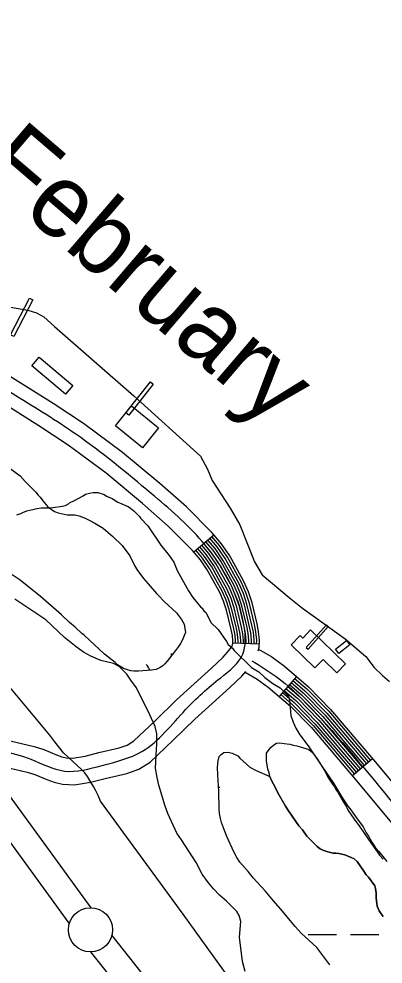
# Model space of a CAD drawing. Extents: x 3161564 to 3199464, y 849354 to 874788.
# Drawn here: x 3177223 to 3177635, y 855355 to 856425 of the extents above; entities that cross this region are included whole.
import ezdxf

# ---------------------------------------------------------------- set-up
doc = ezdxf.new("R2010")
doc.units = 0
for name, color, linetype in [('V-BLDG-OTLN', 7, 'Continuous'), ('V-CHAN-DOCK', 7, 'Continuous'), ('V-LEVE-TOET', 7, 'Continuous'), ('V-RIVR-IDEN', 7, 'Continuous'), ('V-ROAD-CNTR', 7, 'Continuous'), ('V-SITE-VEGE', 7, 'Continuous'), ('V-SURV-LINE', 7, 'Continuous'), ('V-TOPO-SHOR', 7, 'Continuous'), ('V-WETL-SWMP', 7, 'Continuous')]:
    doc.layers.add(name, color=color, linetype=linetype)

msp = doc.modelspace()

# ---------------------------------------------------------------- linework, layer by layer
at = {"layer": 'V-BLDG-OTLN'}
for points in [[(3177276.2, 856000.2), (3177238, 856032.1), (3177246.3, 856042), (3177284.5, 856010.1)], [(3177363.2, 855939.5), (3177332.5, 855964.4), (3177350.6, 855986.8), (3177381.3, 855961.9)], [(3177593, 855694.7), (3177583.2, 855684.6), (3177567.5, 855699.8), (3177558.2, 855690.3), (3177531.3, 855716.4), (3177541.6, 855727), (3177544.6, 855724.1), (3177553.5, 855733.2)]]:
    msp.add_lwpolyline(points, close=True, dxfattribs=at)
at = {"layer": 'V-CHAN-DOCK'}
for points in [[(3177213.9, 856067.4), (3177235.5, 856108.9), (3177239.1, 856107.1), (3177217.6, 856065.5), (3177213.9, 856067.4)], [(3177344.3, 855978.9), (3177372.1, 856014), (3177375.4, 856011.3), (3177347.7, 855976.3), (3177344.3, 855978.9)], [(3177550.8, 855711.3), (3177573.5, 855737.3), (3177571.4, 855739.2), (3177548.6, 855713.2), (3177550.8, 855711.3)], [(3177581.7, 855711.4), (3177594, 855721.1), (3177597.7, 855716.4), (3177585.4, 855706.7), (3177581.7, 855711.4)]]:
    msp.add_lwpolyline(points, dxfattribs=at)
at = {"layer": 'V-LEVE-TOET'}
for points in [[(3177304.8, 855560.8), (3177300.9, 855567.2), (3177297.9, 855571.3), (3177294.1, 855575.4), (3177273.7, 855594.2), (3177264, 855606.4), (3177258.3, 855614.1), (3177215, 855666.3), (3177175.3, 855706.7), (3177129.5, 855747.9), (3177034.4, 855820.9), (3176906.9, 855909.7), (3176744.5, 856013), (3176646.2, 856081), (3176636.6, 856089.2), (3176622.9, 856101.9), (3176611.6, 856113.2), (3176549.5, 856179.9), (3176488.5, 856246.6)], [(3177895, 854786.5), (3177827, 854872.8), (3177751.9, 854967.9), (3177672.1, 855062.6), (3177580.1, 855181.8), (3177482, 855310.4), (3177409.2, 855411.4), (3177315.8, 855539.5), (3177313.2, 855545.8), (3177310, 855552), (3177307.8, 855555.9), (3177304.8, 855560.8)]]:
    msp.add_lwpolyline(points, dxfattribs=at)
at = {"layer": 'V-ROAD-CNTR'}
for p, q in [((3177421.2, 855821.5), (3177444.1, 855840.8)), ((3177465.4, 855718.7), (3177495.4, 855717.4)), ((3177537.3, 855680.7), (3177517.7, 855657.9)), ((3177623.6, 855587.3), (3177600.7, 855567.9))]:
    msp.add_line(p, q, dxfattribs=at)
for points in [[(3177494.1, 855709.5), (3177495.2, 855713.8), (3177495.6, 855721.7), (3177494.6, 855731.4), (3177492.9, 855740.1), (3177487.2, 855764), (3177483, 855776.5), (3177477.6, 855788.9), (3177462, 855817.2), (3177452.5, 855830.8), (3177441.8, 855843.5), (3177412.9, 855872.5), (3177382.8, 855899.2), (3177340.5, 855934.2), (3177296.4, 855967.1), (3177262.1, 855989.6), (3177227.7, 856011.2), (3177194.2, 856031.7)], [(3177207, 855609.1), (3177240.7, 855601.4), (3177251.6, 855597.9), (3177266, 855591.8), (3177272, 855589.6), (3177276.9, 855588.4), (3177284.4, 855588.1), (3177298.3, 855590.3), (3177313.9, 855594.3), (3177336.9, 855599.7), (3177345.9, 855602.9), (3177353.4, 855607.6), (3177377.3, 855630.1), (3177401.6, 855654), (3177421.8, 855672.3), (3177441.6, 855690.2), (3177454.2, 855702.1), (3177459.4, 855707.9), (3177464, 855713.9), (3177464.5, 855714.9), (3177465.4, 855718.3), (3177465.5, 855720.8), (3177464.9, 855727.1), (3177463.6, 855733.8), (3177458.3, 855755.7), (3177455, 855765.8), (3177450.7, 855775.6), (3177436.5, 855801.3), (3177428.7, 855812.6), (3177419.7, 855823.2), (3177392.4, 855850.6), (3177363.2, 855876.4), (3177322, 855910.7), (3177279.2, 855942.5), (3177245.9, 855964.3), (3177211.9, 855985.7)], [(3177477.4, 855718.2), (3177477.5, 855721.2), (3177476.8, 855728.8), (3177475.3, 855736.3), (3177469.9, 855759), (3177466.2, 855770.1), (3177461.5, 855780.9), (3177446.7, 855807.7), (3177438.2, 855819.9), (3177430.3, 855829.2)], [(3177480.4, 855718.1), (3177480.6, 855721.3), (3177479.7, 855729.3), (3177478.3, 855737), (3177472.8, 855759.9), (3177469, 855771.2), (3177464.2, 855782.3), (3177449.2, 855809.3), (3177440.6, 855821.7), (3177432.6, 855831.2)], [(3177483.4, 855717.9), (3177483.6, 855721.4), (3177482.7, 855729.7), (3177481.2, 855737.6), (3177475.7, 855760.7), (3177471.8, 855772.2), (3177466.9, 855783.6), (3177451.8, 855810.9), (3177443, 855823.5), (3177434.9, 855833.1)], [(3177486.4, 855717.8), (3177486.6, 855721.5), (3177485.7, 855730.1), (3177484.1, 855738.2), (3177478.6, 855761.5), (3177474.6, 855773.3), (3177469.6, 855784.9), (3177454.3, 855812.4), (3177445.4, 855825.4), (3177437.2, 855835)], [(3177489.4, 855717.7), (3177489.6, 855721.6), (3177488.7, 855730.6), (3177487.1, 855738.8), (3177481.4, 855762.3), (3177477.4, 855774.4), (3177472.3, 855786.3), (3177456.9, 855814), (3177447.8, 855827.2), (3177439.5, 855837)], [(3177492.4, 855717.6), (3177492.6, 855721.6), (3177491.6, 855731), (3177490, 855739.5), (3177484.3, 855763.2), (3177480.2, 855775.5), (3177474.9, 855787.6), (3177459.4, 855815.6), (3177450.2, 855829), (3177441.8, 855838.9)], [(3177468.4, 855718.6), (3177468.5, 855720.9), (3177467.9, 855727.5), (3177466.5, 855734.4), (3177461.2, 855756.5), (3177457.8, 855766.9), (3177453.4, 855777), (3177439, 855802.9), (3177431.1, 855814.4), (3177423.5, 855823.4)], [(3177471.4, 855718.5), (3177471.5, 855721), (3177470.8, 855728), (3177469.5, 855735.1), (3177464.1, 855757.4), (3177460.6, 855767.9), (3177456.1, 855778.3), (3177441.6, 855804.5), (3177433.5, 855816.2), (3177425.8, 855825.4)], [(3177474.4, 855718.3), (3177474.5, 855721.1), (3177473.8, 855728.4), (3177472.4, 855735.7), (3177467, 855758.2), (3177463.4, 855769), (3177458.8, 855779.6), (3177444.1, 855806.1), (3177435.8, 855818.1), (3177428.1, 855827.3)], [(3177494.6, 855711.3), (3177509.5, 855702.6), (3177523.9, 855692.2), (3177551.2, 855668.7), (3177576.1, 855643.2), (3177624.6, 855586.1), (3177672.3, 855529.2), (3177736.6, 855452.1), (3177800.7, 855374.8)], [(3177188.7, 855582.4), (3177200.4, 855579.8), (3177232.8, 855572.4), (3177241.2, 855569.7), (3177255, 855563.9), (3177263.2, 855560.9), (3177272.7, 855558.6), (3177286.2, 855558), (3177304.5, 855560.9), (3177321, 855565.2), (3177345.4, 855570.9), (3177359, 855575.8), (3177371.8, 855583.7), (3177398.1, 855608.4), (3177422.3, 855632.2), (3177441.9, 855650), (3177461.9, 855668.2), (3177475.6, 855681), (3177480.1, 855686.1)], [(3177479.4, 855685.4), (3177493.1, 855677.4), (3177505.3, 855668.6), (3177530.7, 855646.8), (3177553.9, 855623), (3177601.6, 855566.8), (3177649.3, 855510), (3177713.5, 855432.9), (3177777.6, 855355.6)], [(3177527.5, 855669.3), (3177540.9, 855657.7), (3177565, 855633.1), (3177612.2, 855577.6)], [(3177529.5, 855671.6), (3177543, 855659.9), (3177567.3, 855635.1), (3177614.4, 855579.5)], [(3177531.4, 855673.8), (3177545.1, 855662.1), (3177569.5, 855637.1), (3177616.7, 855581.5)], [(3177533.4, 855676.1), (3177547.1, 855664.3), (3177571.7, 855639.1), (3177619, 855583.4)], [(3177535.3, 855678.4), (3177549.2, 855666.5), (3177573.9, 855641.2), (3177621.3, 855585.4)], [(3177519.7, 855660.2), (3177532.7, 855649), (3177556.2, 855625), (3177603, 855569.8)], [(3177521.6, 855662.5), (3177534.8, 855651.2), (3177558.4, 855627), (3177605.3, 855571.8)], [(3177523.6, 855664.7), (3177536.8, 855653.4), (3177560.6, 855629), (3177607.6, 855573.7)], [(3177525.6, 855667), (3177538.9, 855655.5), (3177562.8, 855631.1), (3177609.9, 855575.6)]]:
    msp.add_lwpolyline(points, dxfattribs=at)
for points in [[(3176879.1, 855651.9), (3176902.3, 855659.1), (3176934.1, 855667), (3176983.4, 855657.7), (3177040.7, 855639.1), (3177110.5, 855613.6), (3177170.6, 855601.8), (3177236.8, 855586.9), (3177274.8, 855573.5), (3177317.4, 855579.8), (3177362.6, 855595.7), (3177412, 855643.1), (3177451.7, 855679.2), (3177476.7, 855705.8), (3177478.3, 855737), (3177464.2, 855782.3), (3177430.8, 855833.4), (3177373, 855887.8), (3177287.8, 855954.8), (3177219.8, 855998.4), (3177153, 856039.4), (3177089.3, 856079.2), (3177023.4, 856134.3), (3176966.6, 856207.9), (3176895.2, 856290.1), (3176782.2, 856425.1), (3176693.2, 856545.3), (3176615.2, 856622.6), (3176543.9, 856726.5), (3176474.4, 856784.2), (3176414.4, 856823.6), (3176395.9, 856828), (3176350.8, 856806.2), (3176279.1, 856754.7), (3176211.6, 856707.4), (3176172.3, 856696.1), (3176141.1, 856702), (3176111.7, 856719.6), (3176032.6, 856777.4), (3175933.6, 856857.4), (3175839, 856930.3), (3175807.1, 856951.5), (3175770.1, 856958.7), (3175787.1, 856991.4), (3175795.1, 857040.7), (3175799.5, 857113.7), (3175810.8, 857206.9), (3175813.7, 857287.4), (3175807.8, 857386.8), (3175805.7, 857497.9), (3175801.9, 857543.6), (3175783.5, 857620.5), (3175760.2, 857716.1), (3175755.3, 857765.5), (3175754.5, 857815.6), (3175751.7, 857884.3), (3175756.3, 858015.5), (3175754.9, 858158.6), (3175753.1, 858270.8), (3175748.6, 858321.7), (3175736.5, 858372), (3175677.2, 858555.5), (3175602.2, 858747.1), (3175558.2, 858866.9), (3175502.5, 858986.2), (3175436.3, 859092.6), (3175371.2, 859185.1), (3175300.7, 859261.6), (3175219.1, 859367.2), (3175166.2, 859443.7), (3175175.3, 859507.1), (3175222, 859537.9), (3175285.3, 859568.3), (3175321.2, 859607.5), (3175310.3, 859667.2), (3175262.4, 859798.6), (3175224.6, 859877.9), (3175174.7, 859982), (3175144.8, 860115.4), (3175122.6, 860284.8), (3175088.4, 860568.6), (3175086.3, 860704.5), (3175072.2, 860854.5), (3175052.5, 860999.9), (3175047.5, 861166.8), (3175053.2, 861343.7), (3175066.7, 861550.4), (3175065.5, 861662.5), (3175040.2, 861767.8), (3175017.8, 861884.2), (3175008.4, 862033.9), (3174979.6, 862160.3), (3174952.1, 862274.6), (3174921.6, 862422.8), (3174897, 862525.5), (3174861.7, 862663.2), (3174841.1, 862738)], [(3177487, 855698.4), (3177514.6, 855680.4), (3177565, 855633.1), (3177660.8, 855519.6), (3177789.2, 855365.2)]]:
    msp.add_spline(points, degree=3, dxfattribs=at)
at = {"layer": 'V-SITE-VEGE'}
for p, q in [((3177286.2, 855879.9), (3177296.2, 855885)), ((3177296.2, 855885), (3177298.7, 855886.9)), ((3177298.7, 855886.9), (3177303.1, 855888.2)), ((3177303.1, 855888.2), (3177307.5, 855888.8)), ((3177307.5, 855888.8), (3177312.5, 855888.9)), ((3177312.5, 855888.9), (3177320, 855886.4)), ((3177320, 855886.4), (3177322.6, 855884.6)), ((3177322.6, 855884.6), (3177328.9, 855882.1)), ((3177258.7, 855871.5), (3177269.9, 855872.8)), ((3177269.9, 855872.8), (3177276.2, 855874.1)), ((3177276.2, 855874.1), (3177279.3, 855876)), ((3177279.3, 855876), (3177280.6, 855877.3)), ((3177280.6, 855877.3), (3177286.2, 855879.9)), ((3177328.9, 855882.1), (3177335.2, 855877.8)), ((3177335.2, 855877.8), (3177338.9, 855876.5)), ((3177338.9, 855876.5), (3177344, 855874.1)), ((3177344, 855874.1), (3177347.1, 855872.8)), ((3177347.1, 855872.8), (3177349.7, 855871)), ((3177221.1, 855863.6), (3177225.4, 855864.9)), ((3177225.4, 855864.9), (3177227.9, 855866.2)), ((3177227.9, 855866.2), (3177232.3, 855868.1)), ((3177232.3, 855868.1), (3177239.2, 855869.4)), ((3177239.2, 855869.4), (3177243.6, 855870.7)), ((3177243.6, 855870.7), (3177248.6, 855871.4)), ((3177248.6, 855871.4), (3177258.7, 855871.5)), ((3177349.7, 855871), (3177353.5, 855867.9)), ((3177353.5, 855867.9), (3177359.8, 855861.6)), ((3177359.8, 855861.6), (3177361, 855859.8)), ((3177361, 855859.8), (3177369.3, 855851)), ((3177369.3, 855851), (3177383.9, 855829.2)), ((3177383.9, 855829.2), (3177393.4, 855817.4)), ((3177393.4, 855817.4), (3177398.5, 855809.9)), ((3177398.5, 855809.9), (3177402.3, 855800.5)), ((3177402.3, 855800.5), (3177415.1, 855777.4)), ((3177415.1, 855777.4), (3177420.1, 855769.9)), ((3177254, 855744.7), (3177218.7, 855768.2)), ((3177420.1, 855769.9), (3177429, 855759.3)), ((3177429, 855759.3), (3177430.9, 855758)), ((3177430.9, 855758), (3177432.8, 855754.9)), ((3177432.8, 855754.9), (3177434.7, 855753)), ((3177274.9, 855724.8), (3177254, 855744.7)), ((3177434.7, 855753), (3177439.2, 855744.9)), ((3177439.2, 855744.9), (3177440.5, 855741.8)), ((3177440.5, 855741.8), (3177448.7, 855733.7)), ((3177448.7, 855733.7), (3177458.2, 855720)), ((3177288.2, 855714.2), (3177274.9, 855724.8)), ((3177296.4, 855708), (3177288.2, 855714.2)), ((3177458.2, 855720), (3177460.1, 855716.9)), ((3177460.1, 855716.9), (3177465.2, 855712.5)), ((3177465.2, 855712.5), (3177467.1, 855710)), ((3177304.6, 855703.7), (3177296.4, 855708)), ((3177315.9, 855698.7), (3177304.6, 855703.7)), ((3177467.1, 855710), (3177486.7, 855690.7)), ((3177330.4, 855695.1), (3177315.9, 855698.7)), ((3177336.7, 855692), (3177330.4, 855695.1)), ((3177345.5, 855683.3), (3177336.7, 855692)), ((3177486.7, 855690.7), (3177494.9, 855685.8)), ((3177350, 855676.4), (3177345.5, 855683.3)), ((3177494.9, 855685.8), (3177501.8, 855679.5)), ((3177501.8, 855679.5), (3177510.7, 855672.7)), ((3177356.3, 855667.7), (3177350, 855676.4)), ((3177510.7, 855672.7), (3177518.9, 855667.7)), ((3177371.6, 855637.1), (3177356.3, 855667.7)), ((3177518.9, 855667.7), (3177522, 855664.6)), ((3177522, 855664.6), (3177528.4, 855658.4)), ((3177528.4, 855658.4), (3177529.7, 855654)), ((3177529.7, 855654), (3177531.1, 855636.5)), ((3177377.4, 855623.9), (3177371.6, 855637.1)), ((3177531.1, 855636.5), (3177533.6, 855629)), ((3177533.6, 855629), (3177536.8, 855622.1)), ((3177379.3, 855615.8), (3177377.4, 855623.9)), ((3177379.4, 855603.9), (3177379.3, 855615.8)), ((3177536.8, 855622.1), (3177541.3, 855614.6)), ((3177541.3, 855614.6), (3177550.8, 855602.1)), ((3177377.8, 855576.9), (3177378.9, 855598.2)), ((3177378.9, 855598.2), (3177379.4, 855603.9)), ((3177550.8, 855602.1), (3177566, 855579)), ((3177379.7, 855566.2), (3177377.8, 855576.9)), ((3177566, 855579), (3177579.4, 855559.7)), ((3177381.7, 855557.4), (3177379.7, 855566.2)), ((3177388.8, 855533.6), (3177381.7, 855557.4)), ((3177579.4, 855559.7), (3177588.3, 855544.7)), ((3177588.3, 855544.7), (3177594.6, 855535.3)), ((3177392, 855525.5), (3177388.8, 855533.6)), ((3177594.6, 855535.3), (3177599.1, 855529.7)), ((3177599.1, 855529.7), (3177604.1, 855522.2)), ((3177402.2, 855503), (3177392, 855525.5)), ((3177604.1, 855522.2), (3177613, 855510.4)), ((3177613, 855510.4), (3177616.2, 855503.5)), ((3177407.3, 855495.5), (3177402.2, 855503)), ((3177616.2, 855503.5), (3177618.8, 855499.7)), ((3177618.8, 855499.7), (3177622.6, 855492.9)), ((3177423.8, 855469.9), (3177407.3, 855495.5)), ((3177622.6, 855492.9), (3177627, 855486.6)), ((3177627, 855486.6), (3177630.8, 855482.3)), ((3177630.8, 855482.3), (3177639.7, 855471)), ((3177430.8, 855456.8), (3177423.8, 855469.9)), ((3177437.8, 855446.8), (3177430.8, 855456.8)), ((3177443.5, 855440), (3177437.8, 855446.8)), ((3177450.5, 855433.1), (3177443.5, 855440)), ((3177458.1, 855426.3), (3177450.5, 855433.1)), ((3177470.1, 855414.4), (3177458.1, 855426.3)), ((3177472.6, 855410.1), (3177470.1, 855414.4)), ((3177474.6, 855403.2), (3177472.6, 855410.1)), ((3177472.8, 855385.6), (3177474.6, 855403.2)), ((3177476.2, 855358), (3177472.8, 855385.6)), ((3177479.4, 855346.7), (3177476.2, 855358))]:
    msp.add_line(p, q, dxfattribs=at)
at = {"layer": 'V-SURV-LINE'}
for points in [[(3177177, 855594.1), (3177304.6, 855418.8)], [(3177280.4, 855401.1), (3177152.7, 855576.4)], [(3177328.5, 855387.4), (3177753.7, 854849.5)], [(3177730.1, 854830.9), (3177304.9, 855368.8)]]:
    msp.add_lwpolyline(points, dxfattribs=at)
msp.add_circle((3177304.3, 855393.8), 25, dxfattribs=at)
at = {"layer": 'V-TOPO-SHOR'}
for points in [[(3176820, 856432.1), (3176835.5, 856422.6), (3176927.1, 856314), (3176937.7, 856303.1), (3176955.6, 856286.8), (3176967, 856280.5), (3176975.6, 856277), (3176991.9, 856271.4), (3177012.5, 856263.5), (3177022.6, 856258.7), (3177030.5, 856252.6), (3177038.5, 856244.6), (3177069.6, 856216), (3177111.9, 856189.1), (3177171, 856131.9), (3177206.5, 856101), (3177213.8, 856098.6), (3177233.3, 856095.3), (3177243.2, 856092.3), (3177251.7, 856087.6), (3177263.6, 856076.8), (3177353.4, 855998.1), (3177429, 855930.1), (3177436.7, 855915.1)], [(3177436.7, 855915.1), (3177441.9, 855902.3), (3177462.3, 855871.2), (3177473.3, 855852.2), (3177489.9, 855810.2), (3177498.5, 855795.7), (3177529.2, 855770), (3177544.1, 855757.8), (3177592.5, 855723.3), (3177615.8, 855703.1), (3177625.3, 855690.9), (3177634.9, 855681.5), (3177642.6, 855675)], [(3177507.3, 855567.5), (3177506.4, 855571.4), (3177504.9, 855575.6), (3177503.7, 855585.2), (3177503.7, 855593.7), (3177506.5, 855597.9), (3177508.7, 855600.5), (3177511.8, 855603), (3177514.9, 855605), (3177518.8, 855605.4), (3177523.6, 855604.8), (3177529.8, 855603.8), (3177533.8, 855602.7), (3177538, 855601.9), (3177543.1, 855600.5), (3177551.3, 855597.7), (3177555.6, 855594.4), (3177558.7, 855590.5), (3177560.7, 855587.4), (3177569, 855574.2), (3177573.8, 855565.5), (3177578.1, 855558.5), (3177580.4, 855555.7), (3177582.4, 855552), (3177584.4, 855549.5), (3177590.7, 855538.3), (3177593.6, 855533.8), (3177596.1, 855529), (3177602.7, 855518.9), (3177609.3, 855510.2), (3177619, 855495.9), (3177629, 855481.6), (3177631.5, 855478.2), (3177635.5, 855473.8)], [(3177635.5, 855408.9), (3177633.2, 855411.7), (3177630.9, 855415.1), (3177628.9, 855420.4), (3177627.7, 855429.7), (3177627.6, 855435.3), (3177627, 855440.4), (3177626.2, 855443.5), (3177618.8, 855453.3), (3177616.5, 855456.1), (3177613.6, 855460), (3177606.2, 855471), (3177602.8, 855474.1), (3177599.4, 855475.7), (3177592, 855478.5), (3177585.3, 855480.1), (3177582.1, 855480.7), (3177578.8, 855480.6), (3177572.8, 855482), (3177567.2, 855483.9), (3177564.3, 855485.3), (3177560.7, 855488.1), (3177554.7, 855494), (3177549.3, 855499.8), (3177544.1, 855506.9), (3177540.2, 855511.6), (3177528.5, 855528.4), (3177525, 855533.8), (3177516.4, 855548.7), (3177513.3, 855555.1), (3177511.3, 855558.5), (3177509.3, 855562.7), (3177507.3, 855567.5)]]:
    msp.add_lwpolyline(points, dxfattribs=at)
at = {"layer": 'V-WETL-SWMP'}
for p, q in [((3177396, 855703.9), (3177396, 855706.5)), ((3177452.1, 855592.4), (3177455.4, 855594.4)), ((3177455.4, 855594.4), (3177460.2, 855595)), ((3177460.2, 855595), (3177464.5, 855593.9)), ((3177464.5, 855593.9), (3177471, 855590.9)), ((3177448, 855578), (3177448.7, 855585)), ((3177448.7, 855585), (3177450.1, 855589.9)), ((3177450.1, 855589.9), (3177452.1, 855592.4)), ((3177471, 855590.9), (3177473.5, 855588.1)), ((3177473.5, 855588.1), (3177484.6, 855577.7)), ((3177448.3, 855568.7), (3177448, 855578)), ((3177484.6, 855577.7), (3177492, 855574.1)), ((3177492, 855574.1), (3177507.3, 855567.5)), ((3177448.9, 855562.8), (3177448.3, 855568.7)), ((3177449.6, 855550.6), (3177448.9, 855562.8)), ((3177507.3, 855567.5), (3177509.3, 855562.7)), ((3177509.3, 855562.7), (3177511.3, 855558.5)), ((3177449.3, 855555.1), (3177450.6, 855555.1)), ((3177449.8, 855530.1), (3177449.6, 855550.6)), ((3177511.3, 855558.5), (3177513.3, 855555.1)), ((3177513.3, 855555.1), (3177516.4, 855548.7)), ((3177516.4, 855548.7), (3177525, 855533.8)), ((3177450.4, 855525.6), (3177449.8, 855530.1)), ((3177525, 855533.8), (3177528.5, 855528.4)), ((3177451.5, 855519.6), (3177450.4, 855525.6)), ((3177452.7, 855515.4), (3177451.5, 855519.6)), ((3177528.5, 855528.4), (3177540.2, 855511.6)), ((3177454.7, 855509.2), (3177452.7, 855515.4)), ((3177458.5, 855499.4), (3177454.7, 855509.2)), ((3177540.2, 855511.6), (3177544.1, 855506.9)), ((3177466.5, 855482), (3177458.5, 855499.4)), ((3177544.1, 855506.9), (3177549.3, 855499.8)), ((3177549.3, 855499.8), (3177554.7, 855494)), ((3177554.7, 855494), (3177560.7, 855488.1)), ((3177560.7, 855488.1), (3177564.3, 855485.3)), ((3177469.9, 855475.8), (3177466.5, 855482)), ((3177473.4, 855470.5), (3177469.9, 855475.8)), ((3177564.3, 855485.3), (3177567.2, 855483.9)), ((3177567.2, 855483.9), (3177572.8, 855482)), ((3177572.8, 855482), (3177578.8, 855480.6)), ((3177578.8, 855480.6), (3177582.1, 855480.7)), ((3177582.1, 855480.7), (3177585.3, 855480.1)), ((3177585.3, 855480.1), (3177592, 855478.5)), ((3177592, 855478.5), (3177599.4, 855475.7)), ((3177599.4, 855475.7), (3177602.8, 855474.1)), ((3177479.6, 855463.2), (3177473.4, 855470.5)), ((3177602.8, 855474.1), (3177606.2, 855471)), ((3177606.2, 855471), (3177613.6, 855460)), ((3177482.8, 855459.8), (3177479.6, 855463.2)), ((3177489, 855452.3), (3177482.8, 855459.8)), ((3177613.6, 855460), (3177616.5, 855456.1)), ((3177616.5, 855456.1), (3177618.8, 855453.3)), ((3177492.7, 855448.1), (3177489, 855452.3)), ((3177502.1, 855438), (3177492.7, 855448.1)), ((3177618.8, 855453.3), (3177626.2, 855443.5)), ((3177511.5, 855426.5), (3177502.1, 855438)), ((3177626.2, 855443.5), (3177627, 855440.4)), ((3177627, 855440.4), (3177627.6, 855435.3)), ((3177627.6, 855435.3), (3177627.7, 855429.7)), ((3177521.5, 855415), (3177511.5, 855426.5)), ((3177627.7, 855429.7), (3177628.9, 855420.4)), ((3177526.9, 855408.3), (3177521.5, 855415)), ((3177628.9, 855420.4), (3177630.9, 855415.1)), ((3177630.9, 855415.1), (3177633.2, 855411.7)), ((3177633.2, 855411.7), (3177635.5, 855408.9)), ((3177536, 855397.6), (3177526.9, 855408.3)), ((3177542.8, 855390.1), (3177536, 855397.6)), ((3177560.5, 855373.9), (3177542.8, 855390.1)), ((3177550.6, 855388.6), (3177582.6, 855388.6)), ((3177598.6, 855388.6), (3177630.6, 855388.6)), ((3177575.3, 855354.3), (3177560.5, 855373.9))]:
    msp.add_line(p, q, dxfattribs=at)
msp.add_lwpolyline([(3177212, 855917), (3177224.7, 855907.8), (3177230.4, 855901.4), (3177242.7, 855889.1), (3177245.2, 855885.7), (3177247.5, 855883.5), (3177250.4, 855879.3), (3177256, 855872.6), (3177263.7, 855867.5), (3177267.7, 855865.9), (3177271.1, 855865.1), (3177278.1, 855863.7), (3177286.6, 855863.5), (3177291.4, 855862.4), (3177298.5, 855859.7), (3177303, 855857.4), (3177309.2, 855854.1), (3177318.6, 855848.3), (3177324.5, 855843.5), (3177329.6, 855839), (3177340.2, 855828.7), (3177348.7, 855817.2), (3177354.2, 855806), (3177357.6, 855800.6), (3177364.7, 855791.1), (3177379, 855774.6), (3177381.5, 855772.3), (3177387.8, 855765.6), (3177401.7, 855752.5), (3177407.4, 855745.2), (3177410.5, 855739.9), (3177411.8, 855730.3), (3177410.4, 855726.9), (3177409, 855722.9), (3177406.2, 855717.8), (3177404, 855714.4), (3177400.6, 855709.9), (3177391.1, 855697.7), (3177388.6, 855694.8), (3177386.1, 855692.6), (3177383.3, 855690.6), (3177378.8, 855688.5), (3177373.5, 855687.7), (3177358.8, 855686.7), (3177353.4, 855686.7), (3177350.1, 855686.9), (3177345, 855688.3), (3177341.6, 855689.7), (3177335.1, 855693.6), (3177332.2, 855696.3), (3177320.3, 855705.8), (3177297.3, 855727.4), (3177294.7, 855729.3), (3177287, 855736.3), (3177280.8, 855741.6), (3177271.4, 855750.3), (3177247.8, 855771), (3177224.8, 855789.7), (3177215.8, 855795.8)], dxfattribs=at)
msp.add_arc((3177340.8, 855671), 35.2, 28.0606, 40.7718, dxfattribs=at)

# ---------------------------------------------------------------- texts
at = {"layer": 'V-RIVR-IDEN'}
msp.add_text('February', height=83, rotation=319.3963, dxfattribs=at).set_placement((3177174.4, 856250.6))

doc.saveas('drawing.dxf')
